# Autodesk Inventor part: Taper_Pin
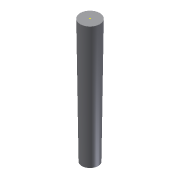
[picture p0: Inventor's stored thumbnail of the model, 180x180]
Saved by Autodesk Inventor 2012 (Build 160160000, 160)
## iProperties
Created: 2011-09
Part Number: Taper_Pin
Material: Default
Document SubType Name: Modeling
Designer: CADCIM
Density: 1 g/cm^3
Author: CADCIM
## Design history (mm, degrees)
sketch "Sketch1"
  geometry: 1 further point
sketch "Sketch2"
  geometry: C1 r 3 at (0, 0); 1 further point
  constraints: 1 centre point, 1 coincident
  dimensions: "d0" = 6 diameter of C1
extrude "Extrusion1" new body sketch "Sketch2" distance "d1" = 38; taper "d2" = -0.75 deg
body "Solid1"
